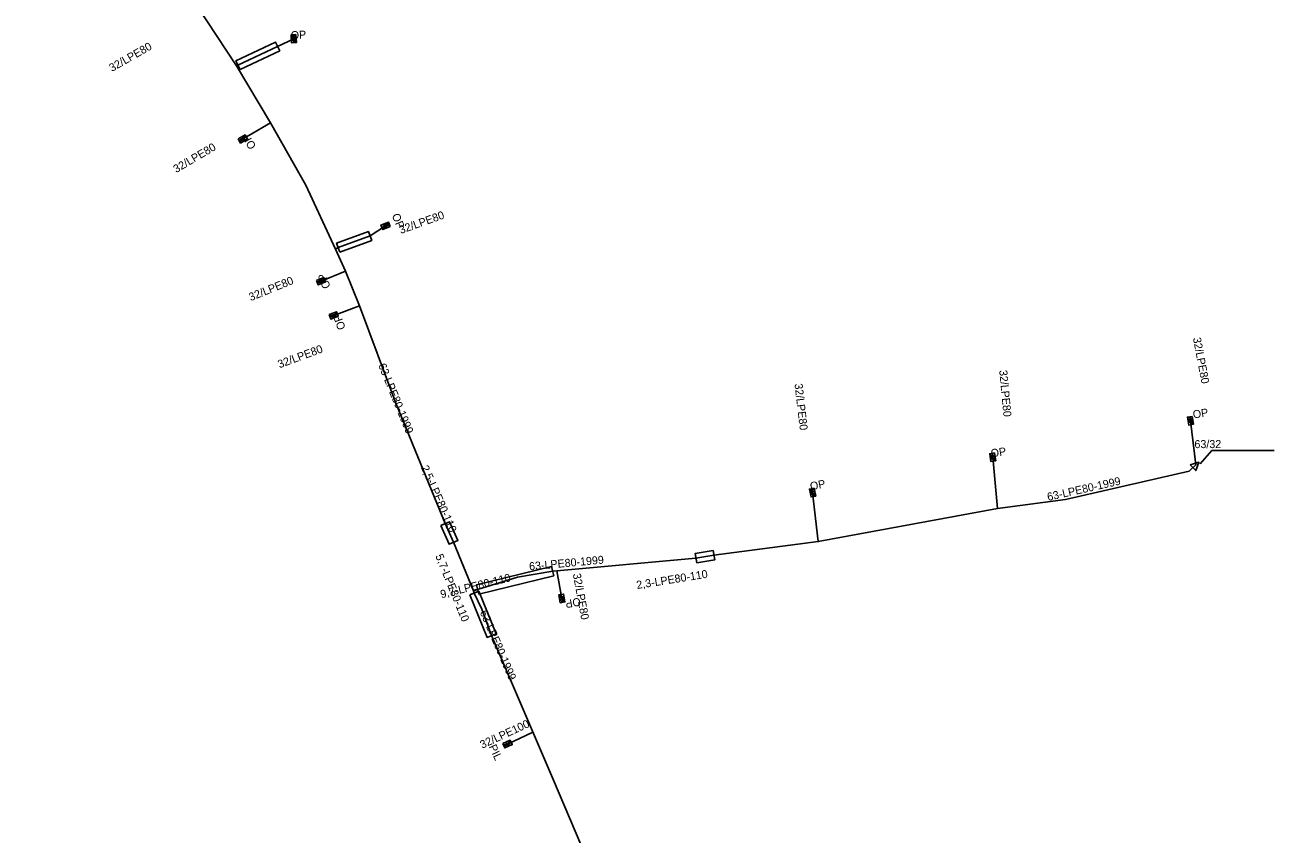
# Model space of a CAD drawing. Extents: x -762509 to -761250, y -1153000 to -1152256.
# Drawn here: x -761555.9 to -761399.8, y -1152659.8 to -1152558.6 of the extents above; entities that cross this region are included whole.
import ezdxf

# ---------------------------------------------------------------- set-up
doc = ezdxf.new("R2010")
doc.units = 0
for name, color, linetype in [('Vrstva 21', 7, 'Continuous'), ('Vrstva 26', 7, 'Continuous'), ('Vrstva 29', 7, 'Continuous'), ('Vrstva 31', 7, 'Continuous'), ('Vrstva 32', 7, 'Continuous')]:
    doc.layers.add(name, color=color, linetype=linetype)

msp = doc.modelspace()

# ---------------------------------------------------------------- linework, layer by layer
at = {"layer": 'Vrstva 21'}
for points in [[(-761555.86, -1152527.89), (-761549.23, -1152535.25), (-761546.63, -1152538.48), (-761545.44, -1152539.91), (-761544.54, -1152541.17), (-761537.84, -1152551.04), (-761536.98, -1152552.22), (-761535.54, -1152554.43), (-761529.45, -1152563.76), (-761525.2, -1152570.86), (-761520.77, -1152578.65), (-761517.06, -1152586.65), (-761515.83, -1152589.42), (-761514.08, -1152593.75), (-761509.53, -1152605.92), (-761503.36, -1152620.97), (-761502.33, -1152623.3), (-761499.83, -1152629.35)], [(-761499.83, -1152629.35), (-761499.32, -1152629.2), (-761494.32, -1152627.65), (-761489.94, -1152626.89), (-761489.43, -1152626.87), (-761472.04, -1152625.27), (-761469.8, -1152624.91), (-761456.76, -1152623.22), (-761434.37, -1152619.07), (-761425.88, -1152617.94), (-761410.43, -1152614.41), (-761409.58, -1152613.63)], [(-761499.83, -1152629.35), (-761499.74, -1152629.64), (-761498.8, -1152631.67), (-761497.58, -1152634.96), (-761489.98, -1152652.74), (-761480.49, -1152675), (-761474.71, -1152689.15), (-761467.61, -1152706.71), (-761461.95, -1152720.82), (-761454.47, -1152739.47), (-761449.55, -1152751.92), (-761449.22, -1152752.61)]]:
    msp.add_lwpolyline(points, dxfattribs=at)
at = {"layer": 'Vrstva 26'}
msp.add_lwpolyline([(-761399.83, -1152611.83), (-761407.59, -1152611.83), (-761409.05, -1152613.48)], dxfattribs=at)
msp.add_lwpolyline([(-761410.287, -1152613.6), (-761409.212, -1152613.292), (-761409.611, -1152614.336)], close=True, dxfattribs=at)
at = {"layer": 'Vrstva 29'}
for points in [[(-761528.99, -1152564.2), (-761524.04, -1152561.86), (-761524.56, -1152560.78), (-761529.51, -1152563.12)], [(-761516.53, -1152587.02), (-761512.55, -1152585.58), (-761512.95, -1152584.46), (-761516.93, -1152585.9)], [(-761503.91, -1152621.21), (-761502.88, -1152623.54), (-761501.78, -1152623.06), (-761502.81, -1152620.73)], [(-761471.94, -1152625.86), (-761469.7, -1152625.5), (-761469.9, -1152624.32), (-761472.14, -1152624.68)], [(-761499.18, -1152629.78), (-761489.8, -1152627.47), (-761490.08, -1152626.31), (-761499.46, -1152628.62)], [(-761500.3, -1152629.87), (-761498.14, -1152635.19), (-761497.02, -1152634.73), (-761499.18, -1152629.41)]]:
    msp.add_lwpolyline(points, close=True, dxfattribs=at)
at = {"layer": 'Vrstva 31'}
for points in [[(-761529.45, -1152563.76), (-761529.25, -1152563.66), (-761524.3, -1152561.32), (-761522.29, -1152560.37)], [(-761525.2, -1152570.86), (-761527.88, -1152572.44), (-761528.64, -1152572.89)], [(-761517.06, -1152586.65), (-761516.73, -1152586.46), (-761512.75, -1152585.02), (-761510.81, -1152583.74)], [(-761515.83, -1152589.42), (-761518.88, -1152590.66)], [(-761514.08, -1152593.75), (-761517.29, -1152594.94)], [(-761409.58, -1152613.63), (-761410.27, -1152608.1)], [(-761434.37, -1152619.07), (-761434.97, -1152612.67)], [(-761456.76, -1152623.22), (-761457.47, -1152617.09)], [(-761489.43, -1152626.87), (-761488.79, -1152630.31)], [(-761492.51, -1152647.09), (-761495.58, -1152648.51)]]:
    msp.add_lwpolyline(points, dxfattribs=at)
at = {"layer": 'Vrstva 32'}
for p, q in [((-761522.138, -1152559.961), (-761522.487, -1152559.98)), ((-761522.476, -1152560.181), (-761522.127, -1152560.161)), ((-761522.453, -1152560.579), (-761522.104, -1152560.56)), ((-761522.303, -1152559.97), (-761522.291, -1152560.171)), ((-761529.083, -1152572.943), (-761528.906, -1152573.244)), ((-761529, -1152573.085), (-761528.826, -1152572.983)), ((-761528.732, -1152573.142), (-761528.91, -1152572.841)), ((-761528.389, -1152572.94), (-761528.566, -1152572.638)), ((-761511.062, -1152583.655), (-761510.928, -1152583.978)), ((-761510.694, -1152583.502), (-761510.559, -1152583.825)), ((-761510.437, -1152583.595), (-761510.623, -1152583.672)), ((-761510.374, -1152583.748), (-761510.508, -1152583.424)), ((-761518.629, -1152590.747), (-761518.761, -1152590.423)), ((-761519.316, -1152590.649), (-761519.185, -1152590.973)), ((-761519.254, -1152590.802), (-761519.068, -1152590.726)), ((-761518.998, -1152590.897), (-761519.13, -1152590.573)), ((-761517.726, -1152594.915), (-761517.604, -1152595.243)), ((-761517.668, -1152595.07), (-761517.48, -1152595)), ((-761517.415, -1152595.173), (-761517.537, -1152594.845)), ((-761517.041, -1152595.035), (-761517.163, -1152594.707)), ((-761410.161, -1152607.678), (-761410.506, -1152607.733)), ((-761410.474, -1152607.932), (-761410.129, -1152607.876)), ((-761410.411, -1152608.325), (-761410.065, -1152608.27)), ((-761410.323, -1152607.704), (-761410.292, -1152607.902)), ((-761434.859, -1152612.248), (-761435.205, -1152612.302)), ((-761435.022, -1152612.274), (-761434.991, -1152612.472)), ((-761435.174, -1152612.501), (-761434.828, -1152612.447)), ((-761435.112, -1152612.895), (-761434.766, -1152612.841)), ((-761457.376, -1152616.663), (-761457.72, -1152616.731)), ((-761457.681, -1152616.928), (-761457.337, -1152616.86)), ((-761457.538, -1152616.695), (-761457.499, -1152616.892)), ((-761457.603, -1152617.32), (-761457.26, -1152617.252)), ((-761488.655, -1152630.081), (-761488.999, -1152630.146)), ((-761488.582, -1152630.473), (-761488.926, -1152630.538)), ((-761488.889, -1152630.735), (-761488.545, -1152630.671)), ((-761488.727, -1152630.705), (-761488.764, -1152630.507)), ((-761496.017, -1152648.52), (-761495.87, -1152648.837)), ((-761495.947, -1152648.669), (-761495.765, -1152648.585)), ((-761495.687, -1152648.753), (-761495.834, -1152648.435)), ((-761495.325, -1152648.585), (-761495.472, -1152648.267))]:
    msp.add_line(p, q, dxfattribs=at)
for points in [[(-761522.019, -1152559.854), (-761521.962, -1152560.852), (-761522.561, -1152560.886), (-761522.618, -1152559.888), (-761522.019, -1152559.854)], [(-761522.121, -1152560.26), (-761522.372, -1152560.274), (-761522.42, -1152560.291), (-761522.451, -1152560.324), (-761522.466, -1152560.367), (-761522.464, -1152560.396), (-761522.445, -1152560.437), (-761522.41, -1152560.464), (-761522.36, -1152560.475), (-761522.11, -1152560.461)], [(-761522.104, -1152560.56), (-761522.097, -1152560.689), (-761522.111, -1152560.732), (-761522.126, -1152560.748), (-761522.158, -1152560.764), (-761522.208, -1152560.767), (-761522.242, -1152560.755), (-761522.259, -1152560.741), (-761522.278, -1152560.7), (-761522.286, -1152560.57)], [(-761529.233, -1152572.886), (-761528.371, -1152572.378), (-761528.067, -1152572.895), (-761528.928, -1152573.403), (-761529.233, -1152572.886)], [(-761528.825, -1152572.79), (-761528.697, -1152573.007), (-761528.66, -1152573.042), (-761528.617, -1152573.054), (-761528.572, -1152573.048), (-761528.547, -1152573.033), (-761528.52, -1152572.997), (-761528.511, -1152572.954), (-761528.524, -1152572.905), (-761528.652, -1152572.688)], [(-761528.566, -1152572.638), (-761528.454, -1152572.572), (-761528.409, -1152572.565), (-761528.388, -1152572.572), (-761528.36, -1152572.593), (-761528.334, -1152572.636), (-761528.33, -1152572.672), (-761528.334, -1152572.693), (-761528.362, -1152572.729), (-761528.474, -1152572.795)], [(-761510.233, -1152583.825), (-761511.156, -1152584.209), (-761511.387, -1152583.655), (-761510.464, -1152583.271), (-761510.233, -1152583.825)], [(-761510.928, -1152583.978), (-761511.048, -1152584.028), (-761511.093, -1152584.029), (-761511.113, -1152584.02), (-761511.138, -1152583.994), (-761511.158, -1152583.948), (-761511.157, -1152583.912), (-761511.15, -1152583.892), (-761511.118, -1152583.86), (-761510.998, -1152583.81)], [(-761510.651, -1152583.863), (-761510.747, -1152583.631), (-761510.779, -1152583.591), (-761510.82, -1152583.573), (-761510.865, -1152583.573), (-761510.892, -1152583.584), (-761510.924, -1152583.616), (-761510.939, -1152583.658), (-761510.933, -1152583.708), (-761510.836, -1152583.94)], [(-761519.456, -1152590.571), (-761518.53, -1152590.194), (-761518.304, -1152590.75), (-761519.23, -1152591.126), (-761519.456, -1152590.571)], [(-761519.038, -1152590.536), (-761518.944, -1152590.768), (-761518.913, -1152590.808), (-761518.871, -1152590.827), (-761518.826, -1152590.827), (-761518.799, -1152590.816), (-761518.767, -1152590.785), (-761518.752, -1152590.743), (-761518.758, -1152590.693), (-761518.852, -1152590.46)], [(-761518.761, -1152590.423), (-761518.64, -1152590.374), (-761518.595, -1152590.374), (-761518.575, -1152590.383), (-761518.55, -1152590.408), (-761518.531, -1152590.455), (-761518.531, -1152590.49), (-761518.539, -1152590.511), (-761518.572, -1152590.542), (-761518.692, -1152590.591)], [(-761517.863, -1152594.833), (-761516.925, -1152594.485), (-761516.717, -1152595.048), (-761517.654, -1152595.395), (-761517.863, -1152594.833)], [(-761517.444, -1152594.811), (-761517.357, -1152595.046), (-761517.327, -1152595.087), (-761517.286, -1152595.107), (-761517.241, -1152595.109), (-761517.214, -1152595.099), (-761517.18, -1152595.068), (-761517.165, -1152595.027), (-761517.169, -1152594.976), (-761517.256, -1152594.741)], [(-761517.163, -1152594.707), (-761517.041, -1152594.661), (-761516.996, -1152594.663), (-761516.976, -1152594.673), (-761516.952, -1152594.699), (-761516.934, -1152594.746), (-761516.936, -1152594.781), (-761516.944, -1152594.802), (-761516.978, -1152594.832), (-761517.1, -1152594.877)], [(-761410.053, -1152607.559), (-761409.894, -1152608.546), (-761410.487, -1152608.642), (-761410.645, -1152607.654), (-761410.053, -1152607.559)], [(-761410.113, -1152607.974), (-761410.361, -1152608.014), (-761410.407, -1152608.035), (-761410.435, -1152608.071), (-761410.445, -1152608.115), (-761410.44, -1152608.144), (-761410.417, -1152608.183), (-761410.38, -1152608.206), (-761410.329, -1152608.212), (-761410.081, -1152608.172)], [(-761410.065, -1152608.27), (-761410.045, -1152608.398), (-761410.055, -1152608.443), (-761410.068, -1152608.46), (-761410.099, -1152608.479), (-761410.148, -1152608.487), (-761410.183, -1152608.478), (-761410.201, -1152608.466), (-761410.225, -1152608.427), (-761410.245, -1152608.299)], [(-761434.751, -1152612.13), (-761434.596, -1152613.118), (-761435.189, -1152613.211), (-761435.344, -1152612.223), (-761434.751, -1152612.13)], [(-761434.812, -1152612.545), (-761435.06, -1152612.583), (-761435.107, -1152612.605), (-761435.134, -1152612.641), (-761435.145, -1152612.685), (-761435.14, -1152612.713), (-761435.117, -1152612.752), (-761435.08, -1152612.776), (-761435.029, -1152612.782), (-761434.781, -1152612.743)], [(-761434.766, -1152612.841), (-761434.746, -1152612.969), (-761434.756, -1152613.013), (-761434.77, -1152613.031), (-761434.8, -1152613.05), (-761434.85, -1152613.057), (-761434.884, -1152613.049), (-761434.902, -1152613.036), (-761434.926, -1152612.998), (-761434.946, -1152612.869)], [(-761457.273, -1152616.541), (-761457.079, -1152617.522), (-761457.668, -1152617.638), (-761457.862, -1152616.657), (-761457.273, -1152616.541)], [(-761457.318, -1152616.958), (-761457.564, -1152617.006), (-761457.61, -1152617.029), (-761457.636, -1152617.066), (-761457.645, -1152617.111), (-761457.639, -1152617.139), (-761457.614, -1152617.177), (-761457.576, -1152617.199), (-761457.525, -1152617.203), (-761457.279, -1152617.155)], [(-761457.26, -1152617.252), (-761457.235, -1152617.379), (-761457.243, -1152617.424), (-761457.256, -1152617.442), (-761457.286, -1152617.462), (-761457.335, -1152617.472), (-761457.37, -1152617.464), (-761457.389, -1152617.453), (-761457.413, -1152617.415), (-761457.439, -1152617.287)], [(-761488.993, -1152630.857), (-761489.177, -1152629.874), (-761488.587, -1152629.763), (-761488.403, -1152630.746), (-761488.993, -1152630.857)], [(-761488.999, -1152630.146), (-761489.023, -1152630.018), (-761489.014, -1152629.973), (-761489.001, -1152629.956), (-761488.971, -1152629.936), (-761488.922, -1152629.927), (-761488.887, -1152629.934), (-761488.869, -1152629.946), (-761488.844, -1152629.984), (-761488.82, -1152630.112)], [(-761488.944, -1152630.44), (-761488.697, -1152630.394), (-761488.652, -1152630.371), (-761488.625, -1152630.335), (-761488.616, -1152630.29), (-761488.621, -1152630.262), (-761488.646, -1152630.224), (-761488.683, -1152630.201), (-761488.734, -1152630.197), (-761488.981, -1152630.243)], [(-761496.16, -1152648.448), (-761495.253, -1152648.028), (-761495, -1152648.572), (-761495.908, -1152648.993), (-761496.16, -1152648.448)], [(-761495.472, -1152648.267), (-761495.354, -1152648.213), (-761495.309, -1152648.211), (-761495.289, -1152648.219), (-761495.262, -1152648.243), (-761495.241, -1152648.288), (-761495.24, -1152648.324), (-761495.247, -1152648.345), (-761495.278, -1152648.378), (-761495.396, -1152648.433)], [(-761495.744, -1152648.394), (-761495.639, -1152648.621), (-761495.606, -1152648.66), (-761495.564, -1152648.677), (-761495.518, -1152648.675), (-761495.492, -1152648.662), (-761495.461, -1152648.629), (-761495.449, -1152648.587), (-761495.457, -1152648.537), (-761495.562, -1152648.309)]]:
    msp.add_lwpolyline(points, dxfattribs=at)

# ---------------------------------------------------------------- texts
at = {"layer": 'Vrstva 21'}
for rotation, p in [(292.292, (-761511.76, -1152601.17)), (12.66775, (-761428.05, -1152618.13)), (5.25681, (-761492.84, -1152626.81)), (293.30239, (-761499.06, -1152632.04))]:
    msp.add_text('63-LPE80-1999', height=1, rotation=rotation, dxfattribs=at).set_placement(p)
at = {"layer": 'Vrstva 26'}
msp.add_text('63/32', height=1, rotation=0.13683, dxfattribs=at).set_placement((-761409.77, -1152611.53))
at = {"layer": 'Vrstva 29'}
for s, rotation, p in [('2,5-LPE80-110', 293.84831, (-761506.42, -1152613.94)), ('5,7-LPE80-110', 292.09789, (-761504.62, -1152625)), ('9,7-LPE80-110', 13.83485, (-761503.84, -1152630.3)), ('2,3-LPE80-110', 9.13018, (-761479.4, -1152629.14))]:
    msp.add_text(s, height=1, rotation=rotation, dxfattribs=at).set_placement(p)
at = {"layer": 'Vrstva 31'}
for s, rotation, p in [('32/LPE80', 29.7785, (-761545, -1152564.53)), ('32/LPE80', 29.7785, (-761545, -1152564.53)), ('32/LPE80', 30.49831, (-761536.97, -1152577.17)), ('32/LPE80', 30.49831, (-761536.97, -1152577.17)), ('32/LPE80', 19.66241, (-761508.91, -1152584.77)), ('32/LPE80', 19.66241, (-761508.91, -1152584.77)), ('32/LPE80', 22.12456, (-761527.66, -1152593.17)), ('32/LPE80', 22.12456, (-761527.66, -1152593.17)), ('32/LPE80', 280.80805, (-761409.97, -1152597.78)), ('32/LPE80', 280.80805, (-761409.97, -1152597.78)), ('32/LPE80', 20.34058, (-761524.07, -1152601.56)), ('32/LPE80', 20.34058, (-761524.07, -1152601.56)), ('32/LPE80', 275.35582, (-761434.16, -1152601.81)), ('32/LPE80', 275.35582, (-761434.16, -1152601.81)), ('32/LPE80', 276.60678, (-761459.73, -1152603.51)), ('32/LPE80', 276.60678, (-761459.73, -1152603.51)), ('32/LPE80', 280.53918, (-761487.43, -1152627.27)), ('32/LPE80', 280.53918, (-761487.43, -1152627.27)), ('32/LPE100', 24.8637, (-761498.74, -1152649.11)), ('32/LPE100', 24.8637, (-761498.74, -1152649.11))]:
    msp.add_text(s, height=1, rotation=rotation, dxfattribs=at).set_placement(p)
at = {"layer": 'Vrstva 32'}
for s, rotation, p in [('OP', 3.25059, (-761522.63, -1152560.44)), ('OP', 3.25059, (-761522.63, -1152560.44)), ('OP', 120.49831, (-761526.94, -1152573.82)), ('OP', 120.49831, (-761526.94, -1152573.82)), ('OP', 292.59953, (-761510.06, -1152582.44)), ('OP', 292.59953, (-761510.06, -1152582.44)), ('OP', 112.12456, (-761517.66, -1152591.36)), ('OP', 112.12456, (-761517.66, -1152591.36)), ('OP', 110.34058, (-761515.78, -1152596.53)), ('OP', 110.34058, (-761515.78, -1152596.53)), ('OP', 9.11924, (-761409.89, -1152607.84)), ('OP', 9.11924, (-761409.89, -1152607.84)), ('OP', 8.89635, (-761435.14, -1152612.69)), ('OP', 8.89635, (-761435.14, -1152612.69)), ('OP', 11.16626, (-761457.69, -1152616.81)), ('OP', 11.16626, (-761457.69, -1152616.81)), ('OP', 190.60027, (-761486.54, -1152630.2)), ('OP', 190.60027, (-761486.54, -1152630.2)), ('PIL', 294.8637, (-761497.95, -1152648.84)), ('PIL', 294.8637, (-761497.95, -1152648.84))]:
    msp.add_text(s, height=1, rotation=rotation, dxfattribs=at).set_placement(p)

doc.saveas('drawing.dxf')
